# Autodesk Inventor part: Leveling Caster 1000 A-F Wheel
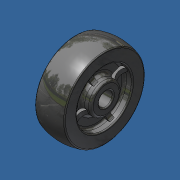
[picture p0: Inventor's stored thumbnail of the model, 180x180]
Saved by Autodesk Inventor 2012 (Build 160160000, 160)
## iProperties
Created: 2015-01
Part Number: Leveling Caster 1000 A-F Wheel
Material: Phenolic
Document SubType Name: Modeling
Designer: Admin
Density: 1.38 g/cm^3
Mass: 111.279 g
Surface Area: 165.372 cm^2
Volume: 80.6367 cm^3
Author: Admin
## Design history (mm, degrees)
feature "Base1"
body "Solid1"
